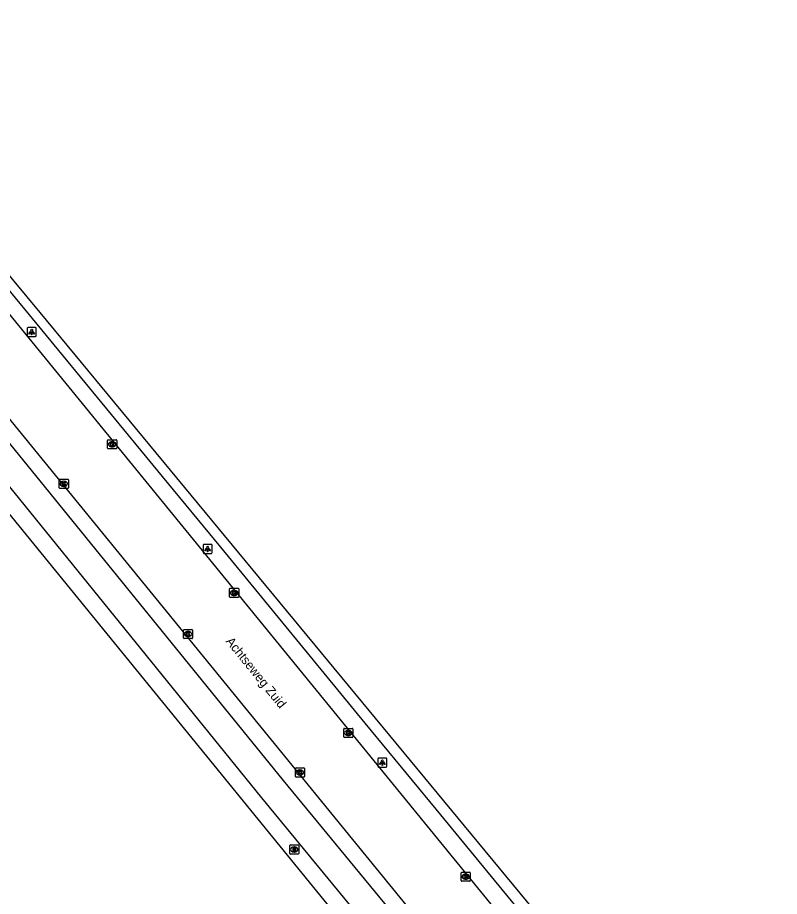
# Model space of a CAD drawing. Extents: x 157154 to 159278, y 385000 to 386650.
# Drawn here: x 158344.1 to 158427.5, y 386325.8 to 386422 of the extents above; entities that cross this region are included whole.
import ezdxf

# ---------------------------------------------------------------- set-up
doc = ezdxf.new("R2010")
doc.units = 0
for name, color, linetype in [('IMGEO_Berm_groen', 7, 'Continuous'), ('IMGEO_Fietspad_gesloten', 7, 'Continuous'), ('IMGEO_Gemengd_bos', 7, 'Continuous'), ('IMGEO_Hek', 7, 'Continuous'), ('IMGEO_Kolk', 7, 'Continuous'), ('IMGEO_Lichtpunt', 7, 'Continuous'), ('IMGEO_Openbare_ruimte_label', 7, 'Continuous'), ('IMGEO_Rijbaan_lokaal_open', 7, 'Continuous'), ('IMGEO_Rioolput', 7, 'Continuous'), ('IMGEO_Spoorbaan_halfverhard', 7, 'Continuous')]:
    doc.layers.add(name, color=color, linetype=linetype)

msp = doc.modelspace()

# ---------------------------------------------------------------- linework, layer by layer
at = {"layer": 'IMGEO_Berm_groen'}
msp.add_lwpolyline([(158427.45, 386289.573), (158423.35, 386294.581), (158412.264, 386308.098), (158389.899, 386335.322), (158382.122, 386344.736), (158366.306, 386364.001), (158359.943, 386371.744), (158320.294, 386419.889), (158310.741, 386431.42), (158304.43, 386439.057), (158293.115, 386452.371), (158288.318, 386457.955)], dxfattribs=at)
at = {"layer": 'IMGEO_Fietspad_gesloten'}
for points in [[(158311.106, 386409.764), (158316.532, 386403.284), (158324.083, 386393.968), (158330.416, 386386.328), (158340.811, 386373.482), (158370.754, 386336.554), (158400.841, 386299.998), (158408.202, 386290.97)], [(158420.154, 386281.193), (158403.187, 386302.007), (158373.17, 386338.476), (158343.241, 386375.349), (158332.917, 386387.935), (158330.194, 386391.292)]]:
    msp.add_lwpolyline(points, dxfattribs=at)
at = {"layer": 'IMGEO_Gemengd_bos'}
msp.add_lwpolyline([(158310.087, 386409.251), (158309.654, 386408.719), (158406.491, 386289.888)], dxfattribs=at)
at = {"layer": 'IMGEO_Hek'}
msp.add_lwpolyline([(158412.264, 386308.098), (158389.899, 386335.322), (158382.122, 386344.736), (158366.306, 386364.001), (158359.943, 386371.744), (158320.294, 386419.889), (158310.741, 386431.42), (158304.43, 386439.057), (158293.115, 386452.371), (158288.318, 386457.955), (158283.695, 386463.336), (158282.157, 386461.93), (158278.128, 386466.274), (158276.042, 386467.327), (158272.251, 386467.953), (158267.264, 386469.128), (158267.021, 386469.184), (158263.452, 386473.157), (158261.818, 386475.083), (158252.208, 386486.509)], dxfattribs=at)
at = {"layer": 'IMGEO_Kolk'}
for p, q in [((158353.93, 386374.844), (158353.93, 386375.696)), ((158354.005, 386375.77), (158354.857, 386375.77)), ((158354.418, 386375.55), (158354.443, 386375.55)), ((158354.931, 386375.696), (158354.931, 386374.844)), ((158354.857, 386374.77), (158354.005, 386374.77)), ((158354.441, 386374.99), (158354.416, 386374.99)), ((158348.632, 386370.509), (158348.632, 386371.361)), ((158348.707, 386371.435), (158349.559, 386371.435)), ((158349.143, 386370.655), (158349.118, 386370.655)), ((158349.12, 386371.215), (158349.145, 386371.215)), ((158349.633, 386371.361), (158349.633, 386370.509)), ((158349.559, 386370.435), (158348.707, 386370.435)), ((158367.275, 386358.575), (158367.275, 386359.427)), ((158367.35, 386359.501), (158368.202, 386359.501)), ((158367.763, 386359.281), (158367.788, 386359.281)), ((158368.276, 386359.427), (158368.276, 386358.575)), ((158368.202, 386358.501), (158367.35, 386358.501)), ((158367.786, 386358.721), (158367.761, 386358.721)), ((158362.235, 386354.066), (158362.235, 386354.918)), ((158362.31, 386354.992), (158363.162, 386354.992)), ((158362.723, 386354.772), (158362.748, 386354.772)), ((158363.236, 386354.918), (158363.236, 386354.066)), ((158363.162, 386353.992), (158362.31, 386353.992)), ((158362.746, 386354.212), (158362.721, 386354.212)), ((158379.771, 386343.245), (158379.771, 386344.097)), ((158379.846, 386344.171), (158380.698, 386344.171)), ((158380.259, 386343.951), (158380.284, 386343.951)), ((158380.772, 386344.097), (158380.772, 386343.245)), ((158380.698, 386343.171), (158379.846, 386343.171)), ((158380.282, 386343.391), (158380.257, 386343.391)), ((158374.556, 386339.842), (158375.408, 386339.842)), ((158374.481, 386338.916), (158374.481, 386339.768)), ((158374.992, 386339.062), (158374.967, 386339.062)), ((158374.969, 386339.622), (158374.994, 386339.622)), ((158375.482, 386339.768), (158375.482, 386338.916)), ((158375.408, 386338.842), (158374.556, 386338.842)), ((158392.621, 386327.506), (158392.621, 386328.358)), ((158392.696, 386328.432), (158393.548, 386328.432)), ((158393.622, 386328.358), (158393.622, 386327.506)), ((158393.548, 386327.432), (158392.696, 386327.432)), ((158393.132, 386327.652), (158393.107, 386327.652)), ((158393.109, 386328.212), (158393.134, 386328.212))]:
    msp.add_line(p, q, dxfattribs=at)
for points in [[(158353.93, 386374.844), (158353.93, 386375.696)], [(158354.005, 386375.77), (158354.857, 386375.77)], [(158354.251, 386375.47), (158354.374, 386375.47), (158354.374, 386375.319), (158354.504, 386375.47), (158354.668, 386375.47), (158354.522, 386375.319), (158354.675, 386375.07), (158354.523, 386375.07), (158354.438, 386375.234), (158354.374, 386375.167), (158354.374, 386375.07), (158354.251, 386375.07), (158354.251, 386375.47)], [(158354.931, 386375.696), (158354.931, 386374.844)], [(158354.857, 386374.77), (158354.005, 386374.77)], [(158348.632, 386370.509), (158348.632, 386371.361)], [(158348.707, 386371.435), (158349.559, 386371.435)], [(158348.953, 386371.135), (158349.076, 386371.135), (158349.076, 386370.984), (158349.206, 386371.135), (158349.37, 386371.135), (158349.224, 386370.984), (158349.377, 386370.735), (158349.225, 386370.735), (158349.14, 386370.899), (158349.076, 386370.832), (158349.076, 386370.735), (158348.953, 386370.735), (158348.953, 386371.135)], [(158349.633, 386371.361), (158349.633, 386370.509)], [(158349.559, 386370.435), (158348.707, 386370.435)], [(158367.275, 386358.575), (158367.275, 386359.427)], [(158367.35, 386359.501), (158368.202, 386359.501)], [(158367.596, 386359.201), (158367.719, 386359.201), (158367.719, 386359.05), (158367.849, 386359.201), (158368.013, 386359.201), (158367.867, 386359.05), (158368.02, 386358.801), (158367.868, 386358.801), (158367.783, 386358.965), (158367.719, 386358.898), (158367.719, 386358.801), (158367.596, 386358.801), (158367.596, 386359.201)], [(158368.276, 386359.427), (158368.276, 386358.575)], [(158368.202, 386358.501), (158367.35, 386358.501)], [(158362.235, 386354.066), (158362.235, 386354.918)], [(158362.31, 386354.992), (158363.162, 386354.992)], [(158362.556, 386354.692), (158362.679, 386354.692), (158362.679, 386354.541), (158362.809, 386354.692), (158362.973, 386354.692), (158362.827, 386354.541), (158362.98, 386354.292), (158362.828, 386354.292), (158362.743, 386354.456), (158362.679, 386354.389), (158362.679, 386354.292), (158362.556, 386354.292), (158362.556, 386354.692)], [(158363.236, 386354.918), (158363.236, 386354.066)], [(158363.162, 386353.992), (158362.31, 386353.992)], [(158379.771, 386343.245), (158379.771, 386344.097)], [(158379.846, 386344.171), (158380.698, 386344.171)], [(158380.092, 386343.871), (158380.215, 386343.871), (158380.215, 386343.72), (158380.345, 386343.871), (158380.509, 386343.871), (158380.363, 386343.72), (158380.516, 386343.471), (158380.364, 386343.471), (158380.279, 386343.635), (158380.215, 386343.568), (158380.215, 386343.471), (158380.092, 386343.471), (158380.092, 386343.871)], [(158380.772, 386344.097), (158380.772, 386343.245)], [(158380.698, 386343.171), (158379.846, 386343.171)], [(158374.556, 386339.842), (158375.408, 386339.842)], [(158374.481, 386338.916), (158374.481, 386339.768)], [(158374.802, 386339.542), (158374.925, 386339.542), (158374.925, 386339.391), (158375.055, 386339.542), (158375.219, 386339.542), (158375.073, 386339.391), (158375.226, 386339.142), (158375.074, 386339.142), (158374.989, 386339.306), (158374.925, 386339.239), (158374.925, 386339.142), (158374.802, 386339.142), (158374.802, 386339.542)], [(158375.482, 386339.768), (158375.482, 386338.916)], [(158375.408, 386338.842), (158374.556, 386338.842)], [(158392.621, 386327.506), (158392.621, 386328.358)], [(158392.696, 386328.432), (158393.548, 386328.432)], [(158393.622, 386328.358), (158393.622, 386327.506)], [(158393.548, 386327.432), (158392.696, 386327.432)], [(158392.942, 386328.132), (158393.065, 386328.132), (158393.065, 386327.981), (158393.195, 386328.132), (158393.359, 386328.132), (158393.213, 386327.981), (158393.366, 386327.732), (158393.214, 386327.732), (158393.129, 386327.896), (158393.065, 386327.829), (158393.065, 386327.732), (158392.942, 386327.732), (158392.942, 386328.132)]]:
    msp.add_lwpolyline(points, dxfattribs=at)
for centre, start, end in [((158354.007, 386375.694), 91.55205, 178.44795), ((158354.007, 386375.694), 91.55205, 178.44795), ((158354.855, 386375.694), 1.55205, 88.44795), ((158354.855, 386375.694), 1.55205, 88.44795), ((158354.007, 386374.846), 181.55205, 268.44795), ((158354.007, 386374.846), 181.55205, 268.44795), ((158354.855, 386374.846), 271.55205, 358.44795), ((158354.855, 386374.846), 271.55205, 358.44795), ((158348.709, 386371.359), 91.55205, 178.44795), ((158348.709, 386371.359), 91.55205, 178.44795), ((158349.557, 386371.359), 1.55205, 88.44795), ((158349.557, 386371.359), 1.55205, 88.44795), ((158348.709, 386370.511), 181.55205, 268.44795), ((158348.709, 386370.511), 181.55205, 268.44795), ((158349.557, 386370.511), 271.55205, 358.44795), ((158349.557, 386370.511), 271.55205, 358.44795), ((158367.352, 386359.425), 91.55205, 178.44795), ((158367.352, 386359.425), 91.55205, 178.44795), ((158368.2, 386359.425), 1.55205, 88.44795), ((158368.2, 386359.425), 1.55205, 88.44795), ((158367.352, 386358.577), 181.55205, 268.44795), ((158367.352, 386358.577), 181.55205, 268.44795), ((158368.2, 386358.577), 271.55205, 358.44795), ((158368.2, 386358.577), 271.55205, 358.44795), ((158362.312, 386354.916), 91.55205, 178.44795), ((158362.312, 386354.916), 91.55205, 178.44795), ((158363.16, 386354.916), 1.55205, 88.44795), ((158363.16, 386354.916), 1.55205, 88.44795), ((158362.312, 386354.068), 181.55205, 268.44795), ((158362.312, 386354.068), 181.55205, 268.44795), ((158363.16, 386354.068), 271.55205, 358.44795), ((158363.16, 386354.068), 271.55205, 358.44795), ((158379.848, 386344.095), 91.55205, 178.44795), ((158379.848, 386344.095), 91.55205, 178.44795), ((158380.696, 386344.095), 1.55205, 88.44795), ((158380.696, 386344.095), 1.55205, 88.44795), ((158379.848, 386343.247), 181.55205, 268.44795), ((158379.848, 386343.247), 181.55205, 268.44795), ((158380.696, 386343.247), 271.55205, 358.44795), ((158380.696, 386343.247), 271.55205, 358.44795), ((158374.558, 386339.766), 91.55205, 178.44795), ((158374.558, 386339.766), 91.55205, 178.44795), ((158375.406, 386339.766), 1.55205, 88.44795), ((158375.406, 386339.766), 1.55205, 88.44795), ((158374.558, 386338.918), 181.55205, 268.44795), ((158374.558, 386338.918), 181.55205, 268.44795), ((158375.406, 386338.918), 271.55205, 358.44795), ((158375.406, 386338.918), 271.55205, 358.44795), ((158392.698, 386328.356), 91.55205, 178.44795), ((158392.698, 386328.356), 91.55205, 178.44795), ((158393.546, 386328.356), 1.55205, 88.44795), ((158393.546, 386328.356), 1.55205, 88.44795), ((158392.698, 386327.508), 181.55205, 268.44795), ((158392.698, 386327.508), 181.55205, 268.44795), ((158393.546, 386327.508), 271.55205, 358.44795), ((158393.546, 386327.508), 271.55205, 358.44795)]:
    msp.add_arc(centre, 0.0765, start, end, dxfattribs=at)
for centre, major_axis, ratio, start_param, end_param in [((158354.417, 386375.27), (-0.387, 0.002), 0.722429, 4.712389, 7.853982), ((158354.442, 386375.27), (-0.39, 0.002), 0.717154, 1.570796, 4.712389), ((158349.119, 386370.935), (-0.387, 0.002), 0.722429, 4.712389, 7.853982), ((158349.144, 386370.935), (-0.39, 0.002), 0.717154, 1.570796, 4.712389), ((158367.762, 386359.001), (-0.387, 0.002), 0.722429, 4.712389, 7.853982), ((158367.787, 386359.001), (-0.39, 0.002), 0.717154, 1.570796, 4.712389), ((158362.722, 386354.492), (-0.387, 0.002), 0.722429, 4.712389, 7.853982), ((158362.747, 386354.492), (-0.39, 0.002), 0.717154, 1.570796, 4.712389), ((158380.258, 386343.671), (-0.387, 0.002), 0.722429, 4.712389, 7.853982), ((158380.283, 386343.671), (-0.39, 0.002), 0.717154, 1.570796, 4.712389), ((158374.968, 386339.342), (-0.387, 0.002), 0.722429, 4.712389, 7.853982), ((158374.993, 386339.342), (-0.39, 0.002), 0.717154, 1.570796, 4.712389), ((158393.108, 386327.932), (-0.387, 0.002), 0.722429, 4.712389, 7.853982), ((158393.133, 386327.932), (-0.39, 0.002), 0.717154, 1.570796, 4.712389)]:
    msp.add_ellipse(centre, major_axis=major_axis, ratio=ratio, start_param=start_param, end_param=end_param, dxfattribs=at)
at = {"layer": 'IMGEO_Lichtpunt'}
for p, q in [((158345.128, 386387.963), (158345.128, 386387.156)), ((158345.128, 386387.963), (158345.128, 386387.156)), ((158346.03, 386388.058), (158345.222, 386388.058)), ((158346.03, 386388.058), (158345.222, 386388.058)), ((158346.124, 386387.156), (158346.124, 386387.963)), ((158346.124, 386387.156), (158346.124, 386387.963)), ((158345.222, 386387.062), (158346.03, 386387.062)), ((158345.222, 386387.062), (158346.03, 386387.062)), ((158364.38, 386364.214), (158364.38, 386363.407)), ((158364.38, 386364.214), (158364.38, 386363.407)), ((158365.282, 386364.309), (158364.474, 386364.309)), ((158365.282, 386364.309), (158364.474, 386364.309)), ((158365.376, 386363.407), (158365.376, 386364.214)), ((158365.376, 386363.407), (158365.376, 386364.214)), ((158364.474, 386363.313), (158365.282, 386363.313)), ((158364.474, 386363.313), (158365.282, 386363.313)), ((158383.497, 386340.826), (158383.497, 386340.019)), ((158383.497, 386340.826), (158383.497, 386340.019)), ((158384.399, 386340.921), (158383.591, 386340.921)), ((158384.399, 386340.921), (158383.591, 386340.921)), ((158384.493, 386340.019), (158384.493, 386340.826)), ((158384.493, 386340.019), (158384.493, 386340.826)), ((158383.591, 386339.925), (158384.399, 386339.925)), ((158383.591, 386339.925), (158384.399, 386339.925))]:
    msp.add_line(p, q, dxfattribs=at)
for points in [[(158345.502, 386387.627), (158345.541, 386387.599), (158345.353, 386387.337), (158345.315, 386387.364), (158345.502, 386387.627)], [(158345.604, 386387.579), (158345.651, 386387.579), (158345.651, 386387.257), (158345.604, 386387.257), (158345.604, 386387.579)], [(158345.714, 386387.599), (158345.752, 386387.626), (158345.939, 386387.364), (158345.9, 386387.336), (158345.714, 386387.599)], [(158364.754, 386363.878), (158364.793, 386363.85), (158364.605, 386363.588), (158364.567, 386363.615), (158364.754, 386363.878)], [(158364.966, 386363.85), (158365.004, 386363.877), (158365.191, 386363.615), (158365.152, 386363.587), (158364.966, 386363.85)], [(158364.856, 386363.83), (158364.903, 386363.83), (158364.903, 386363.508), (158364.856, 386363.508), (158364.856, 386363.83)], [(158383.871, 386340.49), (158383.91, 386340.462), (158383.722, 386340.2), (158383.684, 386340.227), (158383.871, 386340.49)], [(158383.973, 386340.442), (158384.02, 386340.442), (158384.02, 386340.12), (158383.973, 386340.12), (158383.973, 386340.442)], [(158384.083, 386340.462), (158384.121, 386340.489), (158384.308, 386340.227), (158384.269, 386340.199), (158384.083, 386340.462)]]:
    msp.add_lwpolyline(points, dxfattribs=at)
for centre in [(158345.627, 386387.761), (158364.879, 386364.012), (158383.996, 386340.624)]:
    msp.add_circle(centre, 0.0994, dxfattribs=at)
for centre, start, end in [((158345.222, 386387.963), 90, 180), ((158345.222, 386387.963), 90, 180), ((158346.03, 386387.963), 0, 90), ((158346.03, 386387.963), 0, 90), ((158345.222, 386387.156), 180, 270), ((158345.222, 386387.156), 180, 270), ((158346.03, 386387.156), 270, 0), ((158346.03, 386387.156), 270, 360), ((158364.474, 386364.214), 90, 180), ((158364.474, 386364.214), 90, 180), ((158365.282, 386364.214), 0, 90), ((158365.282, 386364.214), 0, 90), ((158364.474, 386363.407), 180, 270), ((158364.474, 386363.407), 180, 270), ((158365.282, 386363.407), 270, 0), ((158365.282, 386363.407), 270, 360), ((158383.591, 386340.826), 90, 180), ((158383.591, 386340.826), 90, 180), ((158384.399, 386340.826), 0, 90), ((158384.399, 386340.826), 0, 90), ((158383.591, 386340.019), 180, 270), ((158383.591, 386340.019), 180, 270), ((158384.399, 386340.019), 270, 0), ((158384.399, 386340.019), 270, 360)]:
    msp.add_arc(centre, 0.0946, start, end, dxfattribs=at)
at = {"layer": 'IMGEO_Rijbaan_lokaal_open'}
for points in [[(158427.029, 386286.802), (158321.486, 386416.081)], [(158331.469, 386392.321), (158421.372, 386282.187)]]:
    msp.add_lwpolyline(points, dxfattribs=at)
at = {"layer": 'IMGEO_Rioolput'}
for p, q in [((158373.855, 386330.487), (158373.855, 386331.339)), ((158373.93, 386331.413), (158374.782, 386331.413)), ((158374.343, 386331.193), (158374.368, 386331.193)), ((158374.856, 386331.339), (158374.856, 386330.487)), ((158374.782, 386330.413), (158373.93, 386330.413)), ((158374.366, 386330.633), (158374.341, 386330.633))]:
    msp.add_line(p, q, dxfattribs=at)
for points in [[(158373.855, 386330.487), (158373.855, 386331.339)], [(158373.93, 386331.413), (158374.782, 386331.413)], [(158374.856, 386331.339), (158374.856, 386330.487)], [(158374.782, 386330.413), (158373.93, 386330.413)], [(158374.444, 386331.111), (158374.192, 386331.113), (158374.192, 386330.713)], [(158374.192, 386330.713), (158374.316, 386330.713), (158374.316, 386330.875), (158374.327, 386330.875)], [(158374.37, 386331.032), (158374.316, 386331.032), (158374.316, 386330.951)], [(158374.316, 386330.951), (158374.368, 386330.951)], [(158374.374, 386330.846), (158374.445, 386330.713), (158374.585, 386330.713), (158374.52, 386330.839)]]:
    msp.add_lwpolyline(points, dxfattribs=at)
for centre, radius, start, end in [((158373.932, 386331.337), 0.0765, 91.55205, 178.44795), ((158373.932, 386331.337), 0.0765, 91.55205, 178.44795), ((158374.78, 386331.337), 0.0765, 1.55205, 88.44795), ((158374.78, 386331.337), 0.0765, 1.55205, 88.44795), ((158373.932, 386330.489), 0.0765, 181.55205, 268.44795), ((158373.932, 386330.489), 0.0765, 181.55205, 268.44795), ((158374.326, 386330.822), 0.0533, 26.02933, 88.69889), ((158374.352, 386331.14), 0.19, 274.7715, 282.96867), ((158374.376, 386330.936), 0.0964, 77.00612, 93.18647), ((158374.39, 386330.993), 0.0378, 276.66336, 79.67722), ((158374.443, 386331.001), 0.109, 350.36119, 89.41601), ((158374.441, 386331.001), 0.112, 277.58423, 350.98172), ((158374.425, 386330.786), 0.108, 29.51342, 73.79051), ((158374.78, 386330.489), 0.0765, 271.55205, 358.44795), ((158374.78, 386330.489), 0.0765, 271.55205, 358.44795)]:
    msp.add_arc(centre, radius, start, end, dxfattribs=at)
for centre, major_axis, ratio, start_param, end_param in [((158374.342, 386330.913), (-0.387, 0.002), 0.722429, 4.712389, 7.853982), ((158374.367, 386330.913), (-0.39, 0.002), 0.717154, 1.570796, 4.712389)]:
    msp.add_ellipse(centre, major_axis=major_axis, ratio=ratio, start_param=start_param, end_param=end_param, dxfattribs=at)
at = {"layer": 'IMGEO_Spoorbaan_halfverhard'}
msp.add_lwpolyline([(158261.201, 386492.741), (158283.609, 386465.705), (158298.814, 386447.192), (158346.523, 386389.687), (158408.781, 386314.342), (158423.503, 386296.229)], dxfattribs=at)

# ---------------------------------------------------------------- texts
at = {"layer": 'IMGEO_Openbare_ruimte_label'}
msp.add_text('Achtseweg Zuid', height=1, rotation=308.95496, dxfattribs=at).set_placement((158366.806, 386353.668))

doc.saveas('drawing.dxf')
